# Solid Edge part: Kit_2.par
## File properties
Last saved by: bmolnar
Revision: 77
Dokumentum tartalom típus: 0
Sűrűség: 0,000 kg/m^3
Pontosság: 0,990
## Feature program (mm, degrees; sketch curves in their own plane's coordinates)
base feature "unnamed BaseFeature 1"
thread "unnamed Thread 1"
sketch for "unnamed Hole 1" plane through (-23.25, -23.25, 90) normal (0, 0, 1) x-axis (0, 1, 0)
  hole centre (0, 0) bore radius 3.3235
hole "unnamed Hole 1" through
sketch for "unnamed Hole 2" plane through (-23.25, -23.25, 90) normal (0, 0, 1) x-axis (0, 1, 0)
  hole centre (46.5, 0) bore radius 3.3235
hole "unnamed Hole 2" through
sketch for "unnamed Hole 3" plane through (-23.25, -23.25, 90) normal (0, 0, 1) x-axis (0, 1, 0)
  hole centre (0, -46.5) bore radius 3.3235
hole "unnamed Hole 3" through
sketch for "unnamed Hole 4" plane through (-23.25, -23.25, 90) normal (0, 0, 1) x-axis (0, 1, 0)
  hole centre (46.5, -46.5) bore radius 3.3235
hole "unnamed Hole 4" through
pattern "unnamed Pattern 1" of "unnamed Hole 1", "unnamed Hole 2", "unnamed Hole 3", "unnamed Hole 4"
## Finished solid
Body 1: solid body, 320 faces, 747 edges, 446 vertices, 4 internal voids.
  Faces by surface: plane 141, cylinder 83, swept 53, torus 22, cone 20, spline 1
  Edges by curve: line 413, circle 177, spline 118, ellipse 28, curve on surface 10, intersection 1
Bounding box of the edges (mm; curved faces can reach further): 65.500 x 65.500 x 14.500, from (-32.75, -32.75, 80.5) to (32.75, 32.75, 95).
Cylindrical faces by radius (mm): R0.2 x40, R0.201 x2, R0.2012 x2, R1.75 x1, R2.5402 x12, R2.6 x4, R3.3235 x4, R3.75 x4, R3.85 x4, R4.283 x1, R5.25 x4, R8.27 x1, R8.85 x1, R9 x1, R10.25 x1, R15.5811 x1
Conical faces (half-angle, radius in mm at the cone's reference point): 0.5 deg R6.5 x2, 0.5 deg R8 x4, 7 deg R9.5925 x1, 14 deg R8.135 x1, 14 deg R8.4811 x1, 17 deg R8.135 x1, 23 deg R8.829 x1, 42.5 deg R8.1233 x1, 45 deg R3.6735 x4, 45 deg R9 x1, 84 deg R8.4608 x1, 85 deg R9.9463 x1, 87 deg R8.1765 x1
Toroidal faces (ring radius, tube radius in mm): R2.9402 r0.4 x12, R3.55 r0.2 x8, R8.8057 r0.2025 x1, R9.2522 r0.2925 x1
Planar faces by outward normal: +x 12, +y 12, +z 24, -x 14, -y 12, -z 1, oblique 66
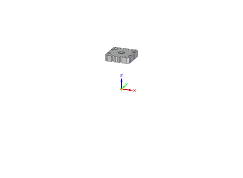
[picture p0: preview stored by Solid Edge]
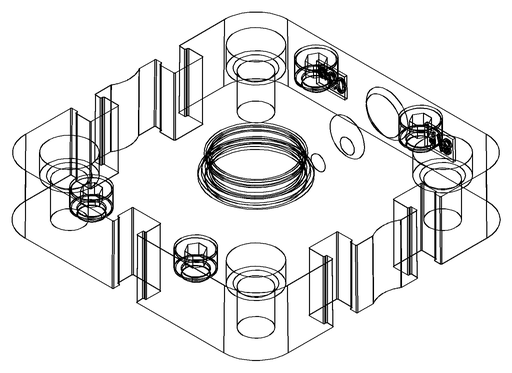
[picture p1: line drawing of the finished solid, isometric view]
